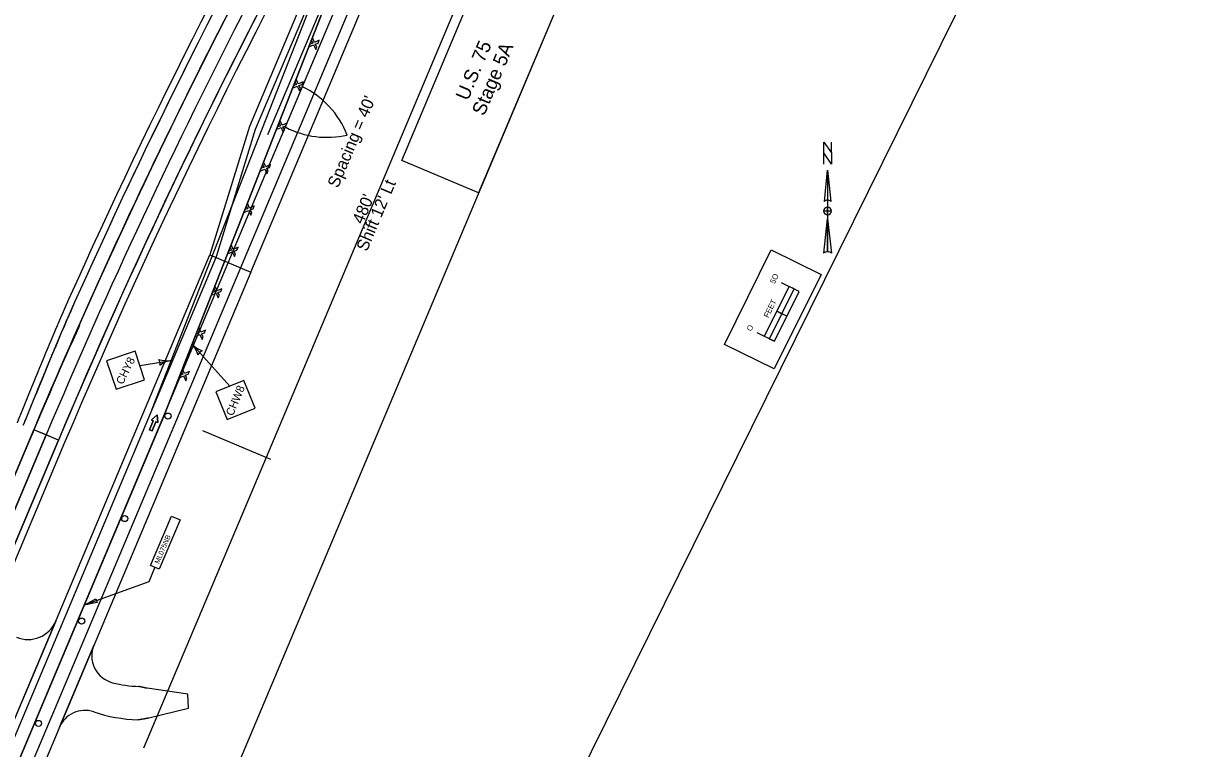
# Model space of a CAD drawing. Extents: x 14104283 to 14129344, y 8637090 to 8673339.
# Drawn here: x 14118644 to 14119692, y 8667727 to 8668379 of the extents above; entities that cross this region are included whole.
import ezdxf

# ---------------------------------------------------------------- set-up
doc = ezdxf.new("R2010")
doc.units = 0
for name, color, linetype in [('Cell', 7, 'Continuous'), ('dsnCellsNorthArrow', 7, 'Continuous'), ('dsnCellsScaleBlock', 7, 'Continuous'), ('dsnNonPlotable', 7, 'Continuous'), ('dsnPaintExistingBrokenLaneLineWhite', 7, 'Continuous'), ('dsnPaintExistingDottedLineWhite', 7, 'Continuous'), ('dsnPaintExistingEdgeLineLeftYellow', 7, 'Continuous'), ('dsnPaintExistingEdgeLineRightWhite', 7, 'Continuous'), ('dsnPaintPlaceChannelizingLaneWhite', 7, 'Continuous'), ('dsnPaintRemoveEdgeLineYellow', 7, 'Continuous'), ('dsnPaintRemoveLaneLineWhite', 7, 'Continuous'), ('dsnShadingPaved', 7, 'Continuous'), ('dsnStdLabel', 7, 'Continuous'), ('dsnStgShadingPrevPav', 7, 'Continuous'), ('dsnTapePlaceChannelizingLaneWhite', 7, 'Continuous'), ('dsnTapePlaceChannelizingLaneYellow', 7, 'Continuous'), ('dsnTextOverlapEven', 7, 'Continuous'), ('Level 2', 7, 'Continuous'), ('Level 5', 7, 'Continuous'), ('Text', 7, 'Continuous')]:
    doc.layers.add(name, color=color, linetype=linetype)

msp = doc.modelspace()

# ---------------------------------------------------------------- linework, layer by layer
at = {"layer": 'Cell'}
for p, q in [((14118901.3, 8668360.6), (14118900.3, 8668358.1)), ((14118900.3, 8668358.1), (14118904.6, 8668360)), ((14118904, 8668361.4), (14118901.3, 8668360.6)), ((14118903.6, 8668366.4), (14118902.6, 8668363.9)), ((14118902.6, 8668363.9), (14118904, 8668361.4)), ((14118905.5, 8668362.1), (14118903.6, 8668366.4)), ((14118904.6, 8668360), (14118906.6, 8668355.6)), ((14118909.8, 8668364), (14118905.5, 8668362.1)), ((14118906.1, 8668360.6), (14118908.8, 8668361.4)), ((14118907.6, 8668358.2), (14118906.1, 8668360.6)), ((14118908.8, 8668361.4), (14118909.8, 8668364)), ((14118906.6, 8668355.6), (14118907.6, 8668358.2)), ((14118889, 8668329.2), (14118888, 8668326.6)), ((14118890.9, 8668324.8), (14118889, 8668329.2)), ((14118886.7, 8668323.4), (14118885.7, 8668320.8)), ((14118885.7, 8668320.8), (14118890, 8668322.7)), ((14118889.4, 8668324.2), (14118886.7, 8668323.4)), ((14118888, 8668326.6), (14118889.4, 8668324.2)), ((14118890, 8668322.7), (14118892, 8668318.4)), ((14118895.2, 8668326.7), (14118890.9, 8668324.8)), ((14118891.5, 8668323.4), (14118894.2, 8668324.2)), ((14118893, 8668320.9), (14118891.5, 8668323.4)), ((14118892, 8668318.4), (14118893, 8668320.9)), ((14118894.2, 8668324.2), (14118895.2, 8668326.7)), ((14118872.1, 8668286.1), (14118871.1, 8668283.6)), ((14118874.8, 8668286.9), (14118872.1, 8668286.1)), ((14118874.4, 8668292), (14118873.4, 8668289.4)), ((14118873.4, 8668289.4), (14118874.8, 8668286.9)), ((14118876.3, 8668287.6), (14118874.4, 8668292)), ((14118880.6, 8668289.5), (14118876.3, 8668287.6)), ((14118876.9, 8668286.1), (14118879.6, 8668286.9)), ((14118878.4, 8668283.7), (14118876.9, 8668286.1)), ((14118879.6, 8668286.9), (14118880.6, 8668289.5)), ((14118871.1, 8668283.6), (14118875.4, 8668285.5)), ((14118875.4, 8668285.5), (14118877.4, 8668281.1)), ((14118877.4, 8668281.1), (14118878.4, 8668283.7)), ((14118859.8, 8668254.7), (14118858.8, 8668252.2)), ((14118861.7, 8668250.3), (14118859.8, 8668254.7)), ((14118857.5, 8668248.9), (14118856.5, 8668246.3)), ((14118856.5, 8668246.3), (14118860.8, 8668248.2)), ((14118860.2, 8668249.7), (14118857.5, 8668248.9)), ((14118858.8, 8668252.2), (14118860.2, 8668249.7)), ((14118860.8, 8668248.2), (14118862.8, 8668243.9)), ((14118866, 8668252.2), (14118861.7, 8668250.3)), ((14118862.3, 8668248.9), (14118865, 8668249.7)), ((14118863.8, 8668246.4), (14118862.3, 8668248.9)), ((14118862.8, 8668243.9), (14118863.8, 8668246.4)), ((14118865, 8668249.7), (14118866, 8668252.2)), ((14118845.6, 8668212.5), (14118842.9, 8668211.7)), ((14118845.2, 8668217.5), (14118844.2, 8668214.9)), ((14118844.2, 8668214.9), (14118845.6, 8668212.5)), ((14118847.1, 8668213.1), (14118845.2, 8668217.5)), ((14118851.4, 8668215), (14118847.1, 8668213.1)), ((14118847.7, 8668211.6), (14118850.4, 8668212.4)), ((14118850.4, 8668212.4), (14118851.4, 8668215)), ((14118842.9, 8668211.7), (14118841.9, 8668209.1)), ((14118841.9, 8668209.1), (14118846.2, 8668211)), ((14118846.2, 8668211), (14118848.2, 8668206.6)), ((14118849.2, 8668209.2), (14118847.7, 8668211.6)), ((14118848.2, 8668206.6), (14118849.2, 8668209.2)), ((14118828.3, 8668174.4), (14118827.3, 8668171.9)), ((14118827.3, 8668171.9), (14118831.6, 8668173.8)), ((14118831, 8668175.2), (14118828.3, 8668174.4)), ((14118830.6, 8668180.2), (14118829.6, 8668177.7)), ((14118829.6, 8668177.7), (14118831, 8668175.2)), ((14118832.5, 8668175.9), (14118830.6, 8668180.2)), ((14118831.6, 8668173.8), (14118833.6, 8668169.4)), ((14118836.8, 8668177.8), (14118832.5, 8668175.9)), ((14118833.1, 8668174.4), (14118835.8, 8668175.2)), ((14118834.6, 8668172), (14118833.1, 8668174.4)), ((14118833.6, 8668169.4), (14118834.6, 8668172)), ((14118835.8, 8668175.2), (14118836.8, 8668177.8)), ((14118816, 8668143), (14118815, 8668140.4)), ((14118815, 8668140.4), (14118816.4, 8668138)), ((14118817.9, 8668138.6), (14118816, 8668143)), ((14118822.2, 8668140.5), (14118817.9, 8668138.6)), ((14118821.2, 8668138), (14118822.2, 8668140.5)), ((14118813.7, 8668137.2), (14118812.7, 8668134.6)), ((14118812.7, 8668134.6), (14118817, 8668136.5)), ((14118816.4, 8668138), (14118813.7, 8668137.2)), ((14118817, 8668136.5), (14118819, 8668132.2)), ((14118818.5, 8668137.2), (14118821.2, 8668138)), ((14118820, 8668134.7), (14118818.5, 8668137.2)), ((14118819, 8668132.2), (14118820, 8668134.7)), ((14118799.1, 8668099.9), (14118798.1, 8668097.4)), ((14118798.1, 8668097.4), (14118802.4, 8668099.3)), ((14118801.8, 8668100.7), (14118799.1, 8668099.9)), ((14118801.4, 8668105.8), (14118800.4, 8668103.2)), ((14118800.4, 8668103.2), (14118801.8, 8668100.7)), ((14118803.3, 8668101.4), (14118801.4, 8668105.8)), ((14118802.4, 8668099.3), (14118804.4, 8668094.9)), ((14118807.6, 8668103.3), (14118803.3, 8668101.4)), ((14118803.9, 8668099.9), (14118806.6, 8668100.7)), ((14118805.4, 8668097.5), (14118803.9, 8668099.9)), ((14118804.4, 8668094.9), (14118805.4, 8668097.5)), ((14118806.6, 8668100.7), (14118807.6, 8668103.3)), ((14118786.8, 8668068.5), (14118785.8, 8668066)), ((14118785.8, 8668066), (14118787.2, 8668063.5)), ((14118788.7, 8668064.1), (14118786.8, 8668068.5)), ((14118793, 8668066), (14118788.7, 8668064.1)), ((14118792, 8668063.5), (14118793, 8668066)), ((14118784.5, 8668062.7), (14118783.5, 8668060.1)), ((14118783.5, 8668060.1), (14118787.8, 8668062)), ((14118787.2, 8668063.5), (14118784.5, 8668062.7)), ((14118787.8, 8668062), (14118789.8, 8668057.7)), ((14118789.3, 8668062.7), (14118792, 8668063.5)), ((14118790.8, 8668060.2), (14118789.3, 8668062.7)), ((14118789.8, 8668057.7), (14118790.8, 8668060.2))]:
    msp.add_line(p, q, dxfattribs=at)
for centre in [(14118773.7, 8668025.9), (14118734.8, 8667933.7), (14118696, 8667841.5), (14118657.2, 8667749.4)]:
    msp.add_circle(centre, 2.75, dxfattribs=at)
at = {"layer": 'dsnCellsNorthArrow'}
for p, q in [((14119367.2, 8668247.1), (14119370, 8668218.9)), ((14119367.2, 8668247.1), (14119367.2, 8668173.8)), ((14119364.4, 8668218.9), (14119364.4, 8668218.9)), ((14119364.5, 8668219.1), (14119365, 8668219.7)), ((14119363.7, 8668172.4), (14119367.2, 8668203.4)), ((14119367.2, 8668206.9), (14119367.2, 8668206.9))]:
    msp.add_line(p, q, dxfattribs=at)
msp.add_lwpolyline([(14119370.7, 8668252.7), (14119363.7, 8668262.6), (14119363.7, 8668272.4), (14119370.7, 8668262.6)], close=True, dxfattribs=at)
for points in [[(14119363.7, 8668252.7), (14119363.7, 8668272.4), (14119370.7, 8668262.6), (14119370.7, 8668272.4)], [(14119364.4, 8668218.9), (14119367.2, 8668247.1), (14119367.2, 8668220.3)], [(14119370.7, 8668210.4), (14119367.2, 8668210.4), (14119367.2, 8668214)], [(14119367.2, 8668206.9), (14119367.2, 8668210.4), (14119363.7, 8668210.4)], [(14119367.2, 8668173.8), (14119367.2, 8668203.4), (14119370.7, 8668172.4)]]:
    msp.add_lwpolyline(points, dxfattribs=at)
for centre, radius, start, end in [((14119367.2, 8668210.4), 3.52, 90, 180), ((14119367.2, 8668216.8), 3.52, 90.0204, 143.1257), ((14119367.2, 8668216.8), 3.52, 36.8481, 90.0218), ((14119367.2, 8668210.4), 3.52, 0, 90), ((14119367.2, 8668210.4), 3.52, 180, 270), ((14119367.2, 8668210.4), 3.52, 270, 360), ((14119367.2, 8668168.7), 5.1, 89.9894, 133.619), ((14119367.2, 8668168.7), 5.11, 46.4021, 90.0006)]:
    msp.add_arc(centre, radius, start, end, dxfattribs=at)
at = {"layer": 'dsnCellsScaleBlock'}
msp.add_line((14119330.4, 8668115.7), (14119321.5, 8668120.2), dxfattribs=at)
msp.add_line((14119330.4, 8668115.7), (14119321.5, 8668120.2), dxfattribs=at)
for points in [[(14119274.4, 8668090.4), (14119316.5, 8668175.6), (14119361.3, 8668153.4), (14119319.2, 8668068.3)], [(14119319.2, 8668068.3), (14119274.4, 8668090.4), (14119316.5, 8668175.6), (14119361.3, 8668153.4)], [(14119325.9, 8668118), (14119337, 8668140.4), (14119332.6, 8668142.6), (14119321.5, 8668120.2)], [(14119319.4, 8668093.3), (14119330.4, 8668115.7), (14119325.9, 8668118), (14119314.8, 8668095.5)]]:
    msp.add_lwpolyline(points, close=True, dxfattribs=at)
for points in [[(14119303.7, 8668101.1), (14119319.4, 8668093.3), (14119341.5, 8668138.1), (14119325.8, 8668145.9)], [(14119310.4, 8668097.7), (14119332.6, 8668142.6)]]:
    msp.add_lwpolyline(points, dxfattribs=at)
at = {"layer": 'dsnNonPlotable'}
for points in [[(14118092, 8667853.7), (14118786.8, 8669258.8), (14119692.1, 8668811.2), (14118997.4, 8667406.1)], [(14118056.5, 8667161.9), (14118665.1, 8668606.4), (14119130.4, 8668410.4), (14118521.9, 8666965.8)]]:
    msp.add_lwpolyline(points, close=True, dxfattribs=at)
at = {"layer": 'dsnPaintExistingBrokenLaneLineWhite'}
for p, q in [((14118863.7, 8668248.6), (14118951.7, 8668457.6)), ((14114932.5, 8658913.4), (14118863.7, 8668248.6)), ((14118664.1, 8668009), (14118424.3, 8667439.6))]:
    msp.add_line(p, q, dxfattribs=at)
msp.add_arc((14123733, 8665874.4), 5500, 152.6921, 157.1633, dxfattribs=at)
at = {"layer": 'dsnPaintExistingDottedLineWhite'}
msp.add_arc((14123733, 8665874.4), 5512, 152.2337, 154.5107, dxfattribs=at)
at = {"layer": 'dsnPaintExistingEdgeLineLeftYellow'}
for p, q in [((14115900.9, 8661244), (14118759.4, 8668031.7)), ((14118675.1, 8668004.3), (14118435.4, 8667434.9))]:
    msp.add_line(p, q, dxfattribs=at)
msp.add_arc((14123733, 8665874.4), 5488, 152.6921, 157.1633, dxfattribs=at)
at = {"layer": 'dsnPaintExistingEdgeLineRightWhite'}
for p, q in [((14118874.7, 8668243.7), (14118962.8, 8668452.9)), ((14110924.4, 8649364.5), (14118874.7, 8668243.7))]:
    msp.add_line(p, q, dxfattribs=at)
for centre, radius, start, end in [((14123733, 8665874.4), 5524, 150.3689, 156.0986), ((14123767.9, 8665959.1), 5522.4, 157.0492, 158.1143)]:
    msp.add_arc(centre, radius, start, end, dxfattribs=at)
at = {"layer": 'dsnPaintPlaceChannelizingLaneWhite'}
for q in [(14118770.5, 8668027.2), (14118537.6, 8667474.2)]:
    msp.add_line((14118767, 8668018.9), q, dxfattribs=at)
at = {"layer": 'dsnPaintRemoveEdgeLineYellow'}
for p, q in [((14118852.6, 8668283.9), (14118948.2, 8668509.9)), ((14118817.4, 8668169.6), (14118852.6, 8668283.9)), ((14118759.4, 8668031.7), (14118817.4, 8668169.6))]:
    msp.add_line(p, q, dxfattribs=at)
at = {"layer": 'dsnPaintRemoveLaneLineWhite'}
msp.add_line((14118863.6, 8668279.3), (14118940.7, 8668462.2), dxfattribs=at)
at = {"layer": 'dsnShadingPaved'}
for p, q in [((14118759.3, 8668031.6), (14118934.6, 8668478.6)), ((14118945.8, 8668474.3), (14118770.5, 8668027.2)), ((14118693.6, 8668107.6), (14118694.1, 8668107.5)), ((14118227.7, 8666769.2), (14118759.4, 8668031.7)), ((14118770.5, 8668027.2), (14118537.6, 8667474.2)), ((14118675.1, 8668004.3), (14118653, 8668013.6)), ((14118646.5, 8667998.1), (14118579.3, 8667838.5))]:
    msp.add_line(p, q, dxfattribs=at)
for points in [[(14118653, 8668013.6), (14118412.9, 8667444.4), (14118424.3, 8667439.6), (14118664.1, 8668009)], [(14118435.4, 8667434.9), (14118675.1, 8668004.3), (14118664.1, 8668009), (14118424.2, 8667439.7)]]:
    msp.add_lwpolyline(points, close=True, dxfattribs=at)
for centre, radius, start, end in [((14123733, 8665874.4), 5512, 149.6777, 156.0986), ((14123733, 8665874.4), 5524, 150.3689, 153.2337), ((14123733, 8665874.4), 5512, 152.6921, 153.1692), ((14123733, 8665874.4), 5488, 152.6921, 157.1633), ((14123733, 8665874.4), 5512, 153.1692, 157.1633), ((14123733, 8665874.4), 5524, 153.2337, 156.0986), ((14123767.9, 8665959.1), 5522.4, 157.0492, 158.1143), ((14123265.6, 8666052.9), 5012, 155.8003, 157.1633)]:
    msp.add_arc(centre, radius, start, end, dxfattribs=at)
at = {"layer": 'dsnStdLabel'}
for p, q in [((14119048.2, 8668430.6), (14118862, 8667988.6)), ((14118829.4, 8668052.9), (14118795.3, 8668090.8)), ((14118748.4, 8668071.4), (14118776.7, 8668075.9)), ((14118866.4, 8667986.8), (14118805.1, 8668012.6)), ((14118862, 8667988.6), (14118751.8, 8667727.1))]:
    msp.add_line(p, q, dxfattribs=at)
for points in [[(14118727.2, 8668050), (14118752.7, 8668058.6), (14118744.1, 8668084.2), (14118718.5, 8668075.5)], [(14118827.1, 8668022.8), (14118852.1, 8668033), (14118841.9, 8668058), (14118816.9, 8668047.8)]]:
    msp.add_lwpolyline(points, close=True, dxfattribs=at)
for centre, radius, start, end in [((14118860.1, 8668249.8), 80.2, 21.0762, 64.7827), ((14118917, 8668358.8), 82.1, 242.911, 282.6274), ((14118778.3, 8668075.4), 22.9, 13.8755, 41.9468), ((14118812.4, 8668106.1), 22.9, 221.9466, 250.0179), ((14118773, 8668098.6), 22.9, 251.0256, 279.0969), ((14118757.7, 8668072.9), 8.86, 351.3626, 26.831), ((14118808.2, 8668076.5), 8.86, 114.2124, 149.6809), ((14118780.3, 8668053.3), 22.9, 99.0968, 127.168)]:
    msp.add_arc(centre, radius, start, end, dxfattribs=at)
at = {"layer": 'dsnStgShadingPrevPav'}
for p, q in [((14118924.1, 8668469.2), (14118847, 8668286.3)), ((14118848.4, 8668155.5), (14118972, 8668449)), ((14118847, 8668286.3), (14118811.5, 8668171)), ((14115895.6, 8661246.8), (14118811.5, 8668171)), ((14118811.5, 8668171), (14118848.4, 8668155.5)), ((14118811.5, 8668171), (14118848.4, 8668155.5)), ((14118848.4, 8668155.5), (14115932.5, 8661231.3)), ((14118653, 8668013.6), (14115794, 8661224.5)), ((14115816.1, 8661215.2), (14118675.1, 8668004.3)), ((14115816.1, 8661215.2), (14118675.1, 8668004.3)), ((14118652.6, 8668013.1), (14118415.9, 8667450.9)), ((14118680.7, 8668002), (14115821.7, 8661212.9)), ((14118672.7, 8667841.4), (14118636.3, 8667754.8)), ((14118707.1, 8667819.9), (14118675.9, 8667745.8)), ((14118791.6, 8667775.6), (14118755.1, 8667781)), ((14118792.2, 8667763.1), (14118791.6, 8667775.6)), ((14118756.4, 8667754.5), (14118792.2, 8667763.1))]:
    msp.add_line(p, q, dxfattribs=at)
for centre, radius, start, end in [((14123733, 8665874.4), 5512, 146.4256, 157.1633), ((14123733, 8665874.4), 5488, 146.4212, 157.1633), ((14123733, 8665874.4), 5530, 150.3689, 156.0991), ((14123733, 8665874.4), 5524, 150.3689, 156.0986), ((14123733, 8665874.4), 5524, 150.3689, 156.0986), ((14123732.6, 8665873.8), 5512, 150.362, 157.1633), ((14123733, 8665874.4), 5482, 150.671, 157.1633), ((14123733, 8665874.4), 5488, 151.143, 157.1633), ((14118647.9, 8667851.9), 27, 247.1633, 337.1633), ((14118730.1, 8667810.2), 25, 157.1633, 255.6089), ((14118750, 8667887.7), 105, 255.6089, 268.5297), ((14118698.9, 8667736.1), 25, 71.3746, 157.1633), ((14118750, 8667887.7), 135, 251.3746, 268.5297)]:
    msp.add_arc(centre, radius, start, end, dxfattribs=at)
for points, degree in [([(14118677.1, 8668114.8), (14118676.8, 8668113.9), (14118675.5, 8668110.8), (14118673.1, 8668105.2), (14118671.2, 8668100.7), (14118669.2, 8668095.9), (14118667.2, 8668091.2), (14118665.2, 8668086.4), (14118663.2, 8668081.7), (14118661.3, 8668076.9), (14118659.3, 8668072.2), (14118657.3, 8668067.4), (14118655.4, 8668062.7), (14118653.4, 8668057.9), (14118651.5, 8668053.2), (14118649.5, 8668048.4), (14118647.6, 8668043.7), (14118645.7, 8668038.9), (14118643.7, 8668034.1), (14118641.9, 8668029.6), (14118639.6, 8668023.9), (14118638.3, 8668020.8), (14118638, 8668019.9)], 2), ([(14118643.5, 8668017.6), (14118644.2, 8668019.2), (14118645.4, 8668022.4), (14118647.4, 8668027.1), (14118649.3, 8668031.9), (14118651.2, 8668036.6), (14118653.1, 8668041.4), (14118655.1, 8668046.2), (14118657, 8668050.9), (14118659, 8668055.7), (14118660.9, 8668060.4), (14118662.9, 8668065.1), (14118664.8, 8668069.9), (14118666.8, 8668074.6), (14118668.8, 8668079.4), (14118670.7, 8668084.1), (14118672.7, 8668088.8), (14118674.7, 8668093.6), (14118676.7, 8668098.3), (14118678.7, 8668103), (14118680.7, 8668107.8), (14118682, 8668110.9), (14118682.7, 8668112.5)], 3), ([(14118643.5, 8668017.6), (14118644.2, 8668019.2), (14118645.4, 8668022.4), (14118647.4, 8668027.1), (14118649.3, 8668031.9), (14118651.2, 8668036.6), (14118653.1, 8668041.4), (14118655.1, 8668046.2), (14118657, 8668050.9), (14118659, 8668055.7), (14118660.9, 8668060.4), (14118662.9, 8668065.1), (14118664.8, 8668069.9), (14118666.8, 8668074.6), (14118668.8, 8668079.4), (14118670.7, 8668084.1), (14118672.7, 8668088.8), (14118674.7, 8668093.6), (14118676.7, 8668098.3), (14118678.7, 8668103), (14118680.7, 8668107.8), (14118682, 8668110.9), (14118682.7, 8668112.5)], 3), ([(14118755.1, 8667781), (14118755, 8667781.1), (14118754.7, 8667781.1), (14118754.3, 8667781.2), (14118754, 8667781.2), (14118753.6, 8667781.3), (14118753.2, 8667781.4), (14118752.8, 8667781.5), (14118752.4, 8667781.6), (14118752, 8667781.6), (14118751.6, 8667781.7), (14118751.2, 8667781.8), (14118750.8, 8667781.9), (14118750.4, 8667782), (14118750, 8667782.1), (14118749.6, 8667782.2), (14118749.2, 8667782.2), (14118748.8, 8667782.3), (14118748.5, 8667782.4), (14118748.1, 8667782.5), (14118747.7, 8667782.6), (14118747.4, 8667782.7), (14118747.3, 8667782.7)], 3), ([(14118746.5, 8667752.7), (14118746.7, 8667752.8), (14118747, 8667752.8), (14118747.5, 8667752.9), (14118748, 8667752.9), (14118748.5, 8667753), (14118749, 8667753.1), (14118749.5, 8667753.2), (14118750, 8667753.3), (14118750.5, 8667753.4), (14118751, 8667753.4), (14118751.5, 8667753.5), (14118752, 8667753.6), (14118752.5, 8667753.7), (14118753, 8667753.8), (14118753.5, 8667753.9), (14118754, 8667754), (14118754.5, 8667754.1), (14118755, 8667754.2), (14118755.4, 8667754.3), (14118755.9, 8667754.4), (14118756.3, 8667754.5), (14118756.4, 8667754.5)], 3)]:
    msp.add_open_spline(points, degree=degree, dxfattribs=at)
at = {"layer": 'dsnTapePlaceChannelizingLaneWhite'}
msp.add_line((14118770.5, 8668027.2), (14118945.8, 8668474.3), dxfattribs=at)
at = {"layer": 'dsnTapePlaceChannelizingLaneYellow'}
msp.add_line((14118759.3, 8668031.6), (14118934.7, 8668478.8), dxfattribs=at)
at = {"layer": 'dsnTextOverlapEven'}
for points in [[(14119130.4, 8668410.4), (14119053.1, 8668226.7), (14118984, 8668255.9), (14119061.3, 8668439.5)], [(14118984, 8668255.9), (14119061.3, 8668439.5), (14119130.4, 8668410.4), (14119053.1, 8668226.7)]]:
    msp.add_lwpolyline(points, close=True, dxfattribs=at)
at = {"layer": 'Level 2'}
msp.add_lwpolyline([(14118757.1, 8668013.6), (14118759.4, 8668012.7), (14118762.8, 8668020.7), (14118764.5, 8668020), (14118764.1, 8668027), (14118758.8, 8668022.4), (14118760.5, 8668021.7)], close=True, dxfattribs=at)
at = {"layer": 'Level 5'}
msp.add_lwpolyline([(14118760.5, 8668021.7), (14118758.8, 8668022.4), (14118764.1, 8668027), (14118764.5, 8668020), (14118762.8, 8668020.7), (14118759.4, 8668012.7), (14118757.1, 8668013.6), (14118760.5, 8668021.7)], dxfattribs=at)
at = {"layer": 'Text'}
for points in [[(14118758.1, 8667891.6), (14118776.8, 8667935.9), (14118784.6, 8667932.7), (14118765.9, 8667888.3)], [(14118758.1, 8667891.6), (14118776.8, 8667935.9), (14118784.6, 8667932.7), (14118765.9, 8667888.3)], [(14118698.3, 8667855.7), (14118708.8, 8667861.4), (14118710, 8667858.1)]]:
    msp.add_lwpolyline(points, close=True, dxfattribs=at)
msp.add_lwpolyline([(14118762, 8667890), (14118756.4, 8667876.8), (14118698.3, 8667855.7)], dxfattribs=at)

# ---------------------------------------------------------------- texts
at = {"layer": 'dsnCellsScaleBlock'}
for s, p in [('5O', (14119319.5, 8668144.5)), ('FEET', (14119313.9, 8668113.9)), ('O', (14119298.5, 8668101.8))]:
    msp.add_text(s, height=5, rotation=63.6912, dxfattribs=at).set_placement(p)
at = {"layer": 'dsnStdLabel'}
for s, height, rotation, p in [("Spacing = 40'", 10.8, 67.1547, (14118926.7, 8668230.4)), ("Shift 12' Lt", 10.8, 67.1547, (14118952.7, 8668173.3)), ("480'", 10.8, 67.1547, (14118949, 8668197.9)), ('CHY8', 7.2, 63.6912, (14118733, 8668053.7)), ('CHW8', 7.2, 67.1547, (14118832.1, 8668025.5))]:
    msp.add_text(s, height=height, rotation=rotation, dxfattribs=at).set_placement(p)
at = {"layer": 'dsnTextOverlapEven'}
for s, p in [('U.S. 75', (14119043.6, 8668308.9)), ('Stage 5A', (14119058.2, 8668295.3))]:
    msp.add_text(s, height=12.5, rotation=67.1547, dxfattribs=at).set_placement(p)
at = {"layer": 'Text'}
msp.add_text('ML075NB', height=4.48, rotation=67.1547, dxfattribs=at).set_placement((14118765.6, 8667892.6))

doc.saveas('drawing.dxf')
